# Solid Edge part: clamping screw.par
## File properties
Author: Deepak Maini
Template: Normal.par
Last saved by: Robert a Rhodes jr
Revision: 4
Application: Solid Edge
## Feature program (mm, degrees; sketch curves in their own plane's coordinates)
sketch for "unnamed RevolvedProtrusion 1" plane through (0, 0, 0) normal (0, -1, 0) x-axis (1, 0, 0)
  line (0, 30.784) -> (7, 30.784)
  line (7, 30.784) -> (7, 20.784)
  line (7, 20.784) -> (13, 20.784)
  line (13, 20.784) -> (13, 14.784)
  line (13, 14.784) -> (8, 14.784)
  line (8, 14.784) -> (8, -9.216)
  line (8, -9.216) -> (0, -9.216)
  line (0, -9.216) -> (0, 30.784)
revolve "unnamed RevolvedProtrusion 1" add full turn 360 deg
sketch for "unnamed Protrusion 1" plane through (0, 0, 0) normal (0, -1, 0) x-axis (1, 0, 0)
  line (-8, 46.784) -> (-8, 30.784)
  line (-8, 30.784) -> (8, 30.784)
  line (8, 30.784) -> (8, 46.784)
  line (8, 46.784) -> (-8, 46.784)
extrude "unnamed Protrusion 1" add finite 16 symmetric
sketch for "unnamed RevolvedCutout 1" #1 plane through (3.6, -3.6, 33.784) normal (-0.707107, -0.707107, 0) x-axis (-0.707107, 0.707107, 0)
  arc centre (13.2152, -0.1884) radius 3.1896 from (13.1274, 3) to (16.4049, -0.1884) cw
  line (17.0244, -0.1884) -> (16.4049, -0.1884)
  line (17.0244, 4.3527) -> (17.0244, -0.1884)
  line (13.1274, 4.3527) -> (17.0244, 4.3527)
  line (13.1274, 3) -> (13.1274, 4.3527)
sketch for "unnamed RevolvedCutout 1" #2 plane through (3.6, -3.6, 33.784) normal (-0.707107, -0.707107, 0) x-axis (-0.707107, 0.707107, 0)
  arc centre (13.1274, -9.7225) radius 3.2775 from (13.1274, -13) to (16.4037, -9.8115) ccw
  line (16.4037, -9.8115) -> (19.2466, -9.8115)
  line (19.2466, -9.8115) -> (19.472, -14.1016)
  line (19.472, -14.1016) -> (13.1274, -14.1016)
  line (13.1274, -14.1016) -> (13.1274, -13)
revolve "unnamed RevolvedCutout 1" cut full turn 360 deg
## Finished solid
Body 1: solid body, 24 faces, 54 edges, 32 vertices.
  Faces by surface: plane 13, torus 8, cylinder 3
  Edges by curve: line 20, circle 18, intersection 16
Bounding box of the edges (mm; curved faces can reach further): 26.000 x 26.000 x 56.006, from (-13, -13, -9.216) to (13, 13, 46.7904).
Cylindrical faces by radius (mm): R7 x1, R8 x1, R13 x1
Toroidal faces (ring radius, tube radius in mm): R8.0362 r3.2775 x4, R8.1241 r3.1896 x4
Planar faces by outward normal: +x 1, +y 1, +z 6, -x 1, -y 1, -z 3
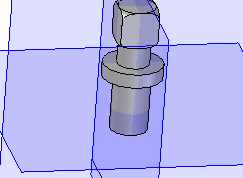
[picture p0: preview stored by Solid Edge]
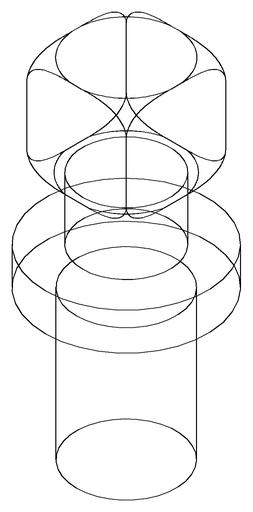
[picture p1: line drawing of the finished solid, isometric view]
